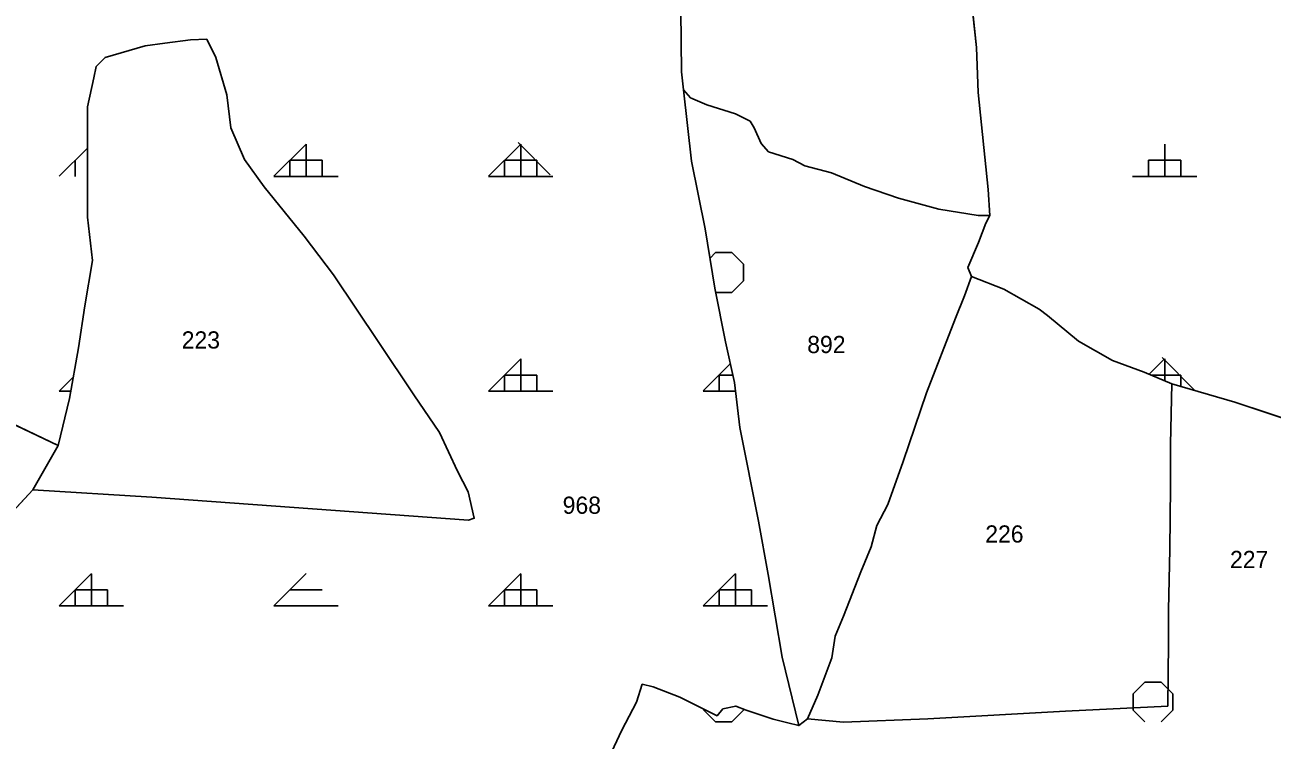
# Model space of a CAD drawing. Extents: x 410727 to 412947, y 4463506 to 4466382.
# Drawn here: x 412447.2 to 412737.7, y 4465954.6 to 4466121.1 of the extents above; entities that cross this region are included whole.
import ezdxf

# ---------------------------------------------------------------- set-up
doc = ezdxf.new("R2010")
doc.units = 0
for name, color, linetype in [('ADAKENARI', 7, 'Continuous'), ('KDS_PARSEL_NO', 7, 'Continuous'), ('KDS_PL', 7, 'Continuous'), ('PL_AYA_ORMAN', 7, 'Continuous'), ('PL_KA_TARIM_DIGER', 7, 'Continuous'), ('TR_ORMAN', 7, 'Continuous'), ('TR_TARIMALANI', 7, 'Continuous')]:
    doc.layers.add(name, color=color, linetype=linetype)

msp = doc.modelspace()

# ---------------------------------------------------------------- linework, layer by layer
at = {"layer": 'ADAKENARI'}
for p, q in [((412668.82, 4466115.88), (412667.54, 4466128.01)), ((412599.98, 4466124.38), (412600.1, 4466110.17)), ((412479.75, 4466116.86), (412475.17, 4466116.24)), ((412485.74, 4466117.65), (412479.75, 4466116.86)), ((412489.53, 4466117.83), (412485.74, 4466117.65)), ((412491.64, 4466113.5), (412489.53, 4466117.83)), ((412491.64, 4466113.5), (412489.53, 4466117.83)), ((412475.17, 4466116.24), (412465.85, 4466113.51)), ((412669.19, 4466105.4), (412668.82, 4466115.88)), ((412463.79, 4466111.45), (412463.2, 4466108.79)), ((412465.85, 4466113.51), (412463.79, 4466111.45)), ((412494.2, 4466104.86), (412491.64, 4466113.5)), ((412463.2, 4466108.79), (412461.73, 4466102.01)), ((412600.1, 4466110.17), (412600.57, 4466106)), ((412600.57, 4466106), (412602.46, 4466089.37)), ((412671.58, 4466082.78), (412669.19, 4466105.4)), ((412495.12, 4466097.18), (412494.2, 4466104.86)), ((412461.73, 4466102.01), (412461.73, 4466088.44)), ((412498.29, 4466089.76), (412495.12, 4466097.18)), ((412461.73, 4466088.44), (412461.72, 4466076.34)), ((412502.87, 4466083.41), (412498.29, 4466089.76)), ((412602.46, 4466089.37), (412605.66, 4466073.66)), ((412512.21, 4466071.93), (412502.87, 4466083.41)), ((412671.94, 4466076.72), (412671.58, 4466082.78)), ((412461.72, 4466076.34), (412462.9, 4466066.31)), ((412671.04, 4466074.95), (412671.94, 4466076.72)), ((412605.66, 4466073.66), (412607.9, 4466059.87)), ((412669.26, 4466070.44), (412671.04, 4466074.95)), ((412669.26, 4466070.44), (412671.04, 4466074.95)), ((412519.08, 4466062.93), (412512.21, 4466071.93)), ((412666.85, 4466064.63), (412669.26, 4466070.44)), ((412462.9, 4466066.31), (412461.14, 4466055.69)), ((412667.65, 4466062.53), (412666.85, 4466064.63)), ((412529.65, 4466047.22), (412519.08, 4466062.93)), ((412675.22, 4466059.63), (412667.65, 4466062.53)), ((412607.9, 4466059.87), (412610.34, 4466047.37)), ((412683.43, 4466054.95), (412675.22, 4466059.63)), ((412461.14, 4466055.69), (412459.66, 4466045.96)), ((412685.36, 4466053.5), (412683.43, 4466054.95)), ((412692.61, 4466047.53), (412685.36, 4466053.5)), ((412537.76, 4466035.04), (412529.65, 4466047.22)), ((412610.34, 4466047.37), (412612.43, 4466037.85)), ((412700.5, 4466043.01), (412692.61, 4466047.53)), ((412459.66, 4466045.96), (412457.6, 4466034.16)), ((412454.95, 4466023.24), (412415.68, 4466041.85)), ((412707.9, 4466040.27), (412700.5, 4466043.01)), ((412714.34, 4466037.53), (412707.9, 4466040.27)), ((412612.43, 4466037.85), (412613.72, 4466027.37)), ((412729.01, 4466033.31), (412714.34, 4466037.53)), ((412457.6, 4466034.16), (412454.95, 4466023.24)), ((412543.75, 4466026.21), (412537.76, 4466035.04)), ((412750.64, 4466026.08), (412729.01, 4466033.31)), ((412613.72, 4466027.37), (412618.07, 4466005.59)), ((412547.97, 4466017.21), (412543.75, 4466026.21)), ((412550.44, 4466012.44), (412547.97, 4466017.21)), ((412419.54, 4465981.17), (412449.06, 4466012.92)), ((412449.06, 4466012.92), (412476.74, 4466011.14)), ((412551.85, 4466006.26), (412550.44, 4466012.44)), ((412476.74, 4466011.14), (412514.13, 4466008.49)), ((412514.13, 4466008.49), (412550.48, 4466005.8)), ((412550.48, 4466005.8), (412551.85, 4466006.26)), ((412618.07, 4466005.59), (412620.32, 4465993.17)), ((412620.32, 4465993.17), (412623.54, 4465973.97)), ((412623.54, 4465973.97), (412627.41, 4465958)), ((412590.99, 4465967.64), (412589.65, 4465963.43)), ((412593.54, 4465967.04), (412590.99, 4465967.64)), ((412599.7, 4465964.63), (412593.54, 4465967.04)), ((412589.65, 4465963.43), (412586.2, 4465956.97)), ((412608.4, 4465960.28), (412599.7, 4465964.63)), ((412609.75, 4465961.93), (412608.4, 4465960.28)), ((412612.75, 4465962.53), (412609.75, 4465961.93)), ((412615.15, 4465961.63), (412612.75, 4465962.53)), ((412621.45, 4465959.52), (412615.15, 4465961.63)), ((412586.2, 4465956.97), (412580.94, 4465945.7)), ((412624.9, 4465958.62), (412621.45, 4465959.52)), ((412627.41, 4465958), (412624.9, 4465958.62))]:
    msp.add_line(p, q, dxfattribs=at)
at = {"layer": 'KDS_PL'}
for p, q in [((412667.54, 4466128.01), (412668.82, 4466115.88)), ((412600.1, 4466110.17), (412599.98, 4466124.38)), ((412475.17, 4466116.24), (412479.75, 4466116.86)), ((412479.75, 4466116.86), (412485.74, 4466117.65)), ((412485.74, 4466117.65), (412489.53, 4466117.83)), ((412489.53, 4466117.83), (412491.64, 4466113.5)), ((412465.85, 4466113.51), (412475.17, 4466116.24)), ((412668.82, 4466115.88), (412669.19, 4466105.4)), ((412463.2, 4466108.79), (412463.79, 4466111.45)), ((412463.79, 4466111.45), (412465.85, 4466113.51)), ((412491.64, 4466113.5), (412494.2, 4466104.86)), ((412461.73, 4466102.01), (412463.2, 4466108.79)), ((412600.57, 4466106), (412600.1, 4466110.17)), ((412602.22, 4466104.12), (412600.57, 4466106)), ((412600.57, 4466106), (412602.46, 4466089.37)), ((412669.19, 4466105.4), (412671.58, 4466082.78)), ((412494.2, 4466104.86), (412495.12, 4466097.18)), ((412605.98, 4466102.55), (412602.22, 4466104.12)), ((412612.72, 4466100.42), (412605.98, 4466102.55)), ((412461.73, 4466088.44), (412461.73, 4466102.01)), ((412616.09, 4466098.7), (412612.72, 4466100.42)), ((412495.12, 4466097.18), (412498.29, 4466089.76)), ((412617.04, 4466097.13), (412616.09, 4466098.7)), ((412618.68, 4466093.51), (412617.04, 4466097.13)), ((412620.41, 4466091.55), (412618.68, 4466093.51)), ((412626.07, 4466089.77), (412620.41, 4466091.55)), ((412461.72, 4466076.34), (412461.73, 4466088.44)), ((412498.29, 4466089.76), (412502.87, 4466083.41)), ((412602.46, 4466089.37), (412605.66, 4466073.66)), ((412628.82, 4466088.3), (412626.07, 4466089.77)), ((412635.06, 4466086.65), (412628.82, 4466088.3)), ((412642.77, 4466083.52), (412635.06, 4466086.65)), ((412502.87, 4466083.41), (412512.21, 4466071.93)), ((412650.66, 4466080.76), (412642.77, 4466083.52)), ((412671.58, 4466082.78), (412671.94, 4466076.72)), ((412660.02, 4466078.19), (412650.66, 4466080.76)), ((412462.9, 4466066.31), (412461.72, 4466076.34)), ((412669.19, 4466076.72), (412660.02, 4466078.19)), ((412671.94, 4466076.72), (412669.19, 4466076.72)), ((412671.04, 4466074.95), (412671.94, 4466076.72)), ((412605.66, 4466073.66), (412607.9, 4466059.87)), ((412669.26, 4466070.44), (412671.04, 4466074.95)), ((412512.21, 4466071.93), (412519.08, 4466062.93)), ((412666.85, 4466064.63), (412669.26, 4466070.44)), ((412461.14, 4466055.69), (412462.9, 4466066.31)), ((412667.65, 4466062.53), (412666.85, 4466064.63)), ((412519.08, 4466062.93), (412529.65, 4466047.22)), ((412666.04, 4466058.01), (412667.65, 4466062.53)), ((412667.65, 4466062.53), (412675.22, 4466059.63)), ((412607.9, 4466059.87), (412610.34, 4466047.37)), ((412675.22, 4466059.63), (412683.43, 4466054.95)), ((412459.66, 4466045.96), (412461.14, 4466055.69)), ((412663.95, 4466052.85), (412666.04, 4466058.01)), ((412657.19, 4466035.43), (412663.95, 4466052.85)), ((412683.43, 4466054.95), (412685.36, 4466053.5)), ((412685.36, 4466053.5), (412692.61, 4466047.53)), ((412529.65, 4466047.22), (412537.76, 4466035.04)), ((412610.34, 4466047.37), (412612.43, 4466037.85)), ((412692.61, 4466047.53), (412700.5, 4466043.01)), ((412457.6, 4466034.16), (412459.66, 4466045.96)), ((412700.5, 4466043.01), (412707.9, 4466040.27)), ((412707.9, 4466040.27), (412714.34, 4466037.53)), ((412612.43, 4466037.85), (412613.72, 4466027.37)), ((412651.72, 4466019.46), (412657.19, 4466035.43)), ((412714.34, 4466037.53), (412714.02, 4466023.49)), ((412714.34, 4466037.53), (412729.01, 4466033.31)), ((412454.95, 4466023.24), (412457.6, 4466034.16)), ((412537.76, 4466035.04), (412543.75, 4466026.21)), ((412729.01, 4466033.31), (412750.64, 4466026.08)), ((412613.72, 4466027.37), (412618.07, 4466005.59)), ((412543.75, 4466026.21), (412547.97, 4466017.21)), ((412449.06, 4466012.92), (412454.95, 4466023.24)), ((412714.02, 4466023.49), (412714.02, 4466013.65)), ((412648.17, 4466009.46), (412651.72, 4466019.46)), ((412547.97, 4466017.21), (412550.44, 4466012.44)), ((412476.74, 4466011.14), (412449.06, 4466012.92)), ((412550.44, 4466012.44), (412551.85, 4466006.26)), ((412714.02, 4466013.65), (412713.86, 4465998.97)), ((412514.13, 4466008.49), (412476.74, 4466011.14)), ((412645.6, 4466004.62), (412648.17, 4466009.46)), ((412550.48, 4466005.8), (412514.13, 4466008.49)), ((412551.85, 4466006.26), (412550.48, 4466005.8)), ((412618.07, 4466005.59), (412620.32, 4465993.17)), ((412644.31, 4465999.62), (412645.6, 4466004.62)), ((412641.9, 4465993.81), (412644.31, 4465999.62)), ((412713.86, 4465998.97), (412713.54, 4465984.94)), ((412620.32, 4465993.17), (412623.54, 4465973.97)), ((412637.87, 4465983.49), (412641.9, 4465993.81)), ((412635.94, 4465978.81), (412637.87, 4465983.49)), ((412713.54, 4465984.94), (412713.54, 4465977.36)), ((412635.13, 4465973.81), (412635.94, 4465978.81)), ((412713.54, 4465977.36), (412713.38, 4465962.52)), ((412623.54, 4465973.97), (412627.41, 4465958)), ((412631.91, 4465965.1), (412635.13, 4465973.81)), ((412590.99, 4465967.64), (412589.65, 4465963.43)), ((412593.54, 4465967.04), (412590.99, 4465967.64)), ((412599.7, 4465964.63), (412593.54, 4465967.04)), ((412589.65, 4465963.43), (412586.2, 4465956.97)), ((412608.4, 4465960.28), (412599.7, 4465964.63)), ((412629.5, 4465959.61), (412631.91, 4465965.1)), ((412609.75, 4465961.93), (412608.4, 4465960.28)), ((412612.75, 4465962.53), (412609.75, 4465961.93)), ((412615.15, 4465961.63), (412612.75, 4465962.53)), ((412621.45, 4465959.52), (412615.15, 4465961.63)), ((412689.55, 4465961.39), (412657.51, 4465959.61)), ((412713.38, 4465962.52), (412689.55, 4465961.39)), ((412586.2, 4465956.97), (412580.94, 4465945.7)), ((412624.9, 4465958.62), (412621.45, 4465959.52)), ((412627.41, 4465958), (412624.9, 4465958.62)), ((412627.41, 4465958), (412629.5, 4465959.61)), ((412637.87, 4465958.81), (412629.5, 4465959.61)), ((412657.51, 4465959.61), (412637.87, 4465958.81))]:
    msp.add_line(p, q, dxfattribs=at)
at = {"layer": 'PL_AYA_ORMAN'}
for points in [[(412667.54, 4466128.01), (412668.82, 4466115.88), (412669.19, 4466105.4), (412671.58, 4466082.78), (412671.94, 4466076.72), (412671.04, 4466074.95), (412669.26, 4466070.44), (412666.85, 4466064.63), (412667.65, 4466062.53), (412675.22, 4466059.63), (412683.43, 4466054.95), (412685.36, 4466053.5), (412692.61, 4466047.53), (412700.5, 4466043.01), (412707.9, 4466040.27), (412714.34, 4466037.53), (412729.01, 4466033.31), (412750.64, 4466026.08)], [(412593.54, 4465967.04), (412599.7, 4465964.63), (412608.4, 4465960.28), (412609.75, 4465961.93), (412612.75, 4465962.53), (412615.15, 4465961.63), (412621.45, 4465959.52), (412624.9, 4465958.62), (412627.41, 4465958), (412623.54, 4465973.97), (412620.32, 4465993.17), (412618.07, 4466005.59), (412613.72, 4466027.37), (412612.43, 4466037.85), (412610.34, 4466047.37), (412607.9, 4466059.87), (412605.66, 4466073.66), (412602.46, 4466089.37), (412600.57, 4466106), (412600.1, 4466110.17), (412599.98, 4466124.38)], [(412415.68, 4466041.85), (412454.95, 4466023.24), (412457.6, 4466034.16), (412459.66, 4466045.96), (412461.14, 4466055.69), (412462.9, 4466066.31), (412461.72, 4466076.34), (412461.73, 4466088.44), (412461.73, 4466102.01), (412463.2, 4466108.79), (412463.79, 4466111.45), (412465.85, 4466113.51), (412475.17, 4466116.24), (412479.75, 4466116.86), (412485.74, 4466117.65), (412489.53, 4466117.83), (412491.64, 4466113.5), (412494.2, 4466104.86), (412495.12, 4466097.18), (412498.29, 4466089.76), (412502.87, 4466083.41), (412512.21, 4466071.93), (412519.08, 4466062.93), (412529.65, 4466047.22), (412537.76, 4466035.04), (412543.75, 4466026.21), (412547.97, 4466017.21), (412550.44, 4466012.44), (412551.85, 4466006.26), (412550.48, 4466005.8), (412514.13, 4466008.49), (412476.74, 4466011.14), (412449.06, 4466012.92), (412419.54, 4465981.17)], [(412580.94, 4465945.7), (412586.2, 4465956.97), (412589.65, 4465963.43), (412590.99, 4465967.64), (412593.54, 4465967.04)]]:
    msp.add_lwpolyline(points, dxfattribs=at)
at = {"layer": 'PL_KA_TARIM_DIGER'}
for points in [[(412667.54, 4466128.01), (412668.82, 4466115.88), (412669.19, 4466105.4), (412671.58, 4466082.78), (412671.94, 4466076.72), (412671.04, 4466074.95), (412669.26, 4466070.44), (412666.85, 4466064.63), (412667.65, 4466062.53), (412675.22, 4466059.63), (412683.43, 4466054.95), (412685.36, 4466053.5), (412692.61, 4466047.53), (412700.5, 4466043.01), (412707.9, 4466040.27), (412714.34, 4466037.53), (412729.01, 4466033.31), (412750.64, 4466026.08)], [(412580.94, 4465945.7), (412586.2, 4465956.97), (412589.65, 4465963.43), (412590.99, 4465967.64), (412593.54, 4465967.04), (412599.7, 4465964.63), (412608.4, 4465960.28), (412609.75, 4465961.93), (412612.75, 4465962.53), (412615.15, 4465961.63), (412621.45, 4465959.52), (412624.9, 4465958.62), (412627.41, 4465958), (412623.54, 4465973.97), (412620.32, 4465993.17), (412618.07, 4466005.59), (412613.72, 4466027.37), (412612.43, 4466037.85), (412610.34, 4466047.37), (412607.9, 4466059.87), (412605.66, 4466073.66), (412602.46, 4466089.37), (412600.57, 4466106), (412600.1, 4466110.17), (412599.98, 4466124.38)], [(412415.68, 4466041.85), (412454.95, 4466023.24), (412457.6, 4466034.16), (412459.66, 4466045.96), (412461.14, 4466055.69), (412462.9, 4466066.31), (412461.72, 4466076.34), (412461.73, 4466088.44), (412461.73, 4466102.01), (412463.2, 4466108.79), (412463.79, 4466111.45), (412465.85, 4466113.51), (412475.17, 4466116.24), (412479.75, 4466116.86), (412485.74, 4466117.65), (412489.53, 4466117.83), (412491.64, 4466113.5), (412494.2, 4466104.86), (412495.12, 4466097.18), (412498.29, 4466089.76), (412502.87, 4466083.41), (412512.21, 4466071.93), (412519.08, 4466062.93), (412529.65, 4466047.22), (412537.76, 4466035.04), (412543.75, 4466026.21), (412547.97, 4466017.21), (412550.44, 4466012.44), (412551.85, 4466006.26), (412550.48, 4466005.8), (412514.13, 4466008.49), (412476.74, 4466011.14), (412449.06, 4466012.92), (412419.54, 4465981.17)]]:
    msp.add_lwpolyline(points, dxfattribs=at)
at = {"layer": 'TR_ORMAN'}
for p, q in [((412505.16, 4466085.88), (412512.66, 4466093.37)), ((412512.67, 4466085.86), (412512.67, 4466093.36)), ((412512.67, 4466085.86), (412512.67, 4466093.36)), ((412555.16, 4466085.88), (412562.66, 4466093.38)), ((412569.55, 4466086.23), (412562.05, 4466093.72)), ((412562.67, 4466085.86), (412562.67, 4466093.36)), ((412562.67, 4466085.86), (412562.67, 4466093.36)), ((412712.67, 4466085.86), (412712.67, 4466093.36)), ((412455.16, 4466085.87), (412461.73, 4466092.43)), ((412458.92, 4466085.86), (412458.92, 4466089.61)), ((412508.92, 4466085.86), (412508.92, 4466089.61)), ((412508.92, 4466085.86), (412508.92, 4466089.61)), ((412508.92, 4466089.61), (412516.42, 4466089.61)), ((412516.42, 4466085.86), (412516.42, 4466089.61)), ((412516.42, 4466085.86), (412516.42, 4466089.61)), ((412558.92, 4466085.86), (412558.92, 4466089.61)), ((412558.92, 4466085.86), (412558.92, 4466089.61)), ((412558.92, 4466089.61), (412566.42, 4466089.61)), ((412566.42, 4466085.86), (412566.42, 4466089.61)), ((412566.42, 4466085.86), (412566.42, 4466089.61)), ((412708.92, 4466085.86), (412708.92, 4466089.61)), ((412708.92, 4466089.61), (412716.42, 4466089.61)), ((412708.92, 4466089.61), (412716.42, 4466089.61)), ((412716.42, 4466085.86), (412716.42, 4466089.61)), ((412505.17, 4466085.86), (412520.17, 4466085.86)), ((412555.17, 4466085.86), (412570.17, 4466085.86)), ((412705.17, 4466085.86), (412720.17, 4466085.86)), ((412705.17, 4466085.86), (412720.17, 4466085.86)), ((412555.16, 4466035.89), (412562.66, 4466043.39)), ((412562.67, 4466035.86), (412562.67, 4466043.36)), ((412562.67, 4466035.86), (412562.67, 4466043.36)), ((412605.16, 4466035.9), (412611.47, 4466042.21)), ((412709.03, 4466039.79), (412712.66, 4466043.41)), ((412719.56, 4466036.2), (412712.06, 4466043.7)), ((412712.67, 4466038.24), (412712.67, 4466043.36)), ((412455.16, 4466035.88), (412458.48, 4466039.2)), ((412558.92, 4466035.86), (412558.92, 4466039.61)), ((412558.92, 4466035.86), (412558.92, 4466039.61)), ((412558.92, 4466039.61), (412566.42, 4466039.61)), ((412566.42, 4466035.86), (412566.42, 4466039.61)), ((412566.42, 4466035.86), (412566.42, 4466039.61)), ((412608.92, 4466035.86), (412608.92, 4466039.61)), ((412608.92, 4466039.61), (412612.05, 4466039.61)), ((412709.45, 4466039.61), (412716.42, 4466039.61)), ((412709.45, 4466039.61), (412716.42, 4466039.61)), ((412716.42, 4466036.93), (412716.42, 4466039.61)), ((412455.17, 4466035.86), (412457.9, 4466035.86)), ((412555.17, 4466035.86), (412570.17, 4466035.86)), ((412605.17, 4466035.86), (412612.68, 4466035.86)), ((412612.67, 4466035.86), (412612.67, 4466035.95)), ((412720.14, 4466035.86), (412720.17, 4466035.86)), ((412720.14, 4466035.86), (412720.17, 4466035.86)), ((412455.16, 4465985.88), (412462.66, 4465993.38)), ((412462.67, 4465985.86), (412462.67, 4465993.36)), ((412505.16, 4465985.89), (412512.66, 4465993.39)), ((412555.16, 4465985.9), (412562.66, 4465993.4)), ((412562.67, 4465985.86), (412562.67, 4465993.36)), ((412562.67, 4465985.86), (412562.67, 4465993.36)), ((412605.16, 4465985.9), (412612.66, 4465993.4)), ((412612.67, 4465985.86), (412612.67, 4465993.36)), ((412458.92, 4465985.86), (412458.92, 4465989.61)), ((412458.92, 4465989.61), (412466.42, 4465989.61)), ((412466.42, 4465985.86), (412466.42, 4465989.61)), ((412508.92, 4465989.61), (412516.42, 4465989.61)), ((412558.92, 4465985.86), (412558.92, 4465989.61)), ((412558.92, 4465985.86), (412558.92, 4465989.61)), ((412558.92, 4465989.61), (412566.42, 4465989.61)), ((412566.42, 4465985.86), (412566.42, 4465989.61)), ((412566.42, 4465985.86), (412566.42, 4465989.61)), ((412608.92, 4465985.86), (412608.92, 4465989.61)), ((412608.92, 4465989.61), (412616.42, 4465989.61)), ((412616.42, 4465985.86), (412616.42, 4465989.61)), ((412455.17, 4465985.86), (412470.17, 4465985.86)), ((412505.17, 4465985.86), (412520.17, 4465985.86)), ((412555.17, 4465985.86), (412570.17, 4465985.86)), ((412605.17, 4465985.86), (412620.17, 4465985.86))]:
    msp.add_line(p, q, dxfattribs=at)
at = {"layer": 'TR_TARIMALANI'}
for p, q in [((412606.77, 4466066.83), (412608.03, 4466068.1)), ((412608.03, 4466068.1), (412611.86, 4466068.1)), ((412614.57, 4466065.39), (412611.86, 4466068.1)), ((412614.57, 4466061.56), (412614.57, 4466065.39)), ((412611.86, 4466058.85), (412614.57, 4466061.56)), ((412608.1, 4466058.85), (412611.86, 4466058.85)), ((412705.32, 4465965.39), (412708.03, 4465968.1)), ((412708.03, 4465968.1), (412711.86, 4465968.1)), ((412714.57, 4465965.39), (412711.86, 4465968.1)), ((412705.32, 4465961.56), (412705.32, 4465965.39)), ((412714.57, 4465961.56), (412714.57, 4465965.39)), ((412605.32, 4465961.56), (412605.32, 4465961.81)), ((412608.03, 4465958.85), (412605.32, 4465961.56)), ((412611.86, 4465958.85), (412614.57, 4465961.56)), ((412614.57, 4465961.56), (412614.57, 4465961.84)), ((412708.03, 4465958.85), (412705.32, 4465961.56)), ((412711.86, 4465958.85), (412714.57, 4465961.56)), ((412608.03, 4465958.85), (412611.86, 4465958.85))]:
    msp.add_line(p, q, dxfattribs=at)

# ---------------------------------------------------------------- texts
at = {"layer": 'KDS_PARSEL_NO'}
for s, p in [('223', (412483.7, 4466045.78)), ('892', (412629.4, 4466044.72)), ('968', (412572.44, 4466007.31)), ('226', (412670.87, 4466000.61)), ('227', (412727.88, 4465994.68))]:
    msp.add_text(s, height=4, dxfattribs=at).set_placement(p)

doc.saveas('drawing.dxf')
